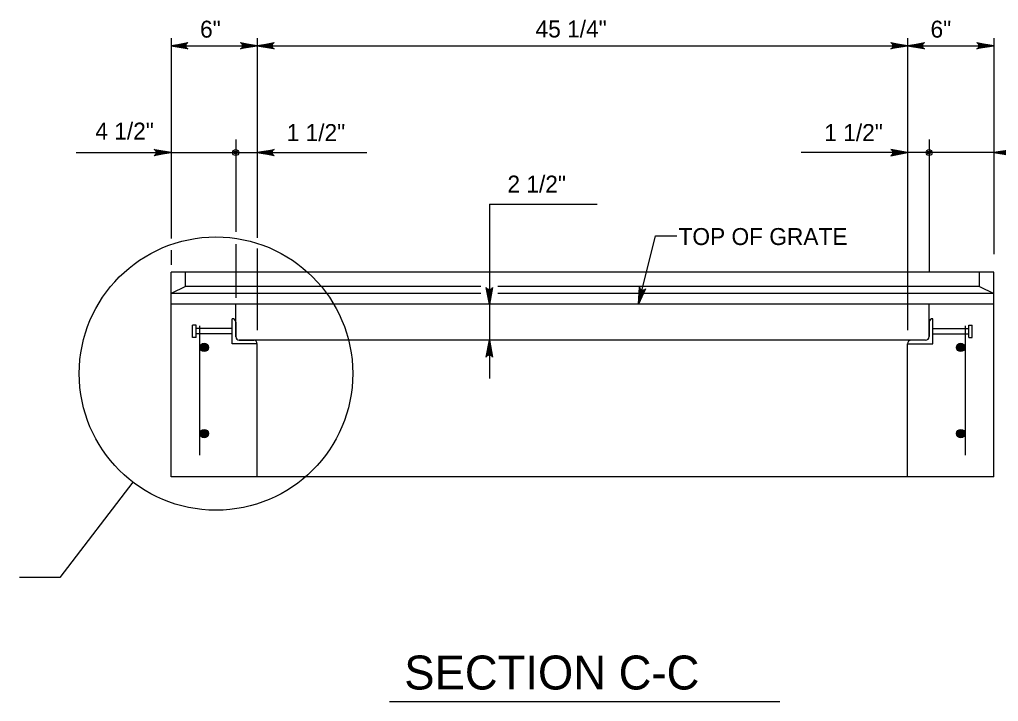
# Model space of a CAD drawing. Extents: x 2087776 to 2104538, y 970919 to 982612.
# Drawn here: x 2094744 to 2095312, y 981338 to 981734 of the extents above; entities that cross this region are included whole.
import ezdxf

# ---------------------------------------------------------------- set-up
doc = ezdxf.new("R2010")
doc.units = 0
doc.layers.add('1', color=7, linetype='Continuous')

msp = doc.modelspace()

# ---------------------------------------------------------------- linework, layer by layer
at = {"layer": '1'}
for p, q in [((2094831.77, 981722.86), (2094831.77, 981606.57)), ((2094881.77, 981722.86), (2094881.77, 981607.02)), ((2095258.86, 981722.86), (2095258.86, 981553.42)), ((2095308.85, 981722.86), (2095308.85, 981597.51)), ((2094831.77, 981718.46), (2095308.85, 981718.46)), ((2094869.27, 981664.01), (2094869.27, 981610.58)), ((2095271.36, 981664.01), (2095271.36, 981587.33)), ((2094776.78, 981656.53), (2094945.26, 981656.53)), ((2095370.41, 981656.53), (2095197.18, 981656.53)), ((2095016.35, 981626.49), (2095016.35, 981525.48)), ((2095016.35, 981626.49), (2095078.81, 981626.49)), ((2094869.27, 981603.46), (2094869.27, 981572.27)), ((2094831.77, 981599.9), (2094831.77, 981591.41)), ((2094881.77, 981600.79), (2094881.77, 981553.42)), ((2094831.77, 981468.46), (2094831.77, 981587.21)), ((2095308.85, 981587.21), (2094831.77, 981587.21)), ((2094840.1, 981578.87), (2094840.1, 981587.21)), ((2095300.52, 981578.87), (2095300.52, 981587.21)), ((2095308.85, 981468.46), (2095308.85, 981587.21)), ((2094840.1, 981578.87), (2094831.77, 981574.71)), ((2095011.44, 981574.71), (2094831.77, 981574.71)), ((2095011.44, 981578.87), (2094840.1, 981578.87)), ((2095300.52, 981578.87), (2095021.18, 981578.87)), ((2095308.85, 981574.71), (2095021.18, 981574.71)), ((2095300.52, 981578.87), (2095308.85, 981574.71)), ((2095308.85, 981568.46), (2094831.77, 981568.46)), ((2094869.27, 981549.66), (2094869.27, 981568.46)), ((2095271.36, 981549.72), (2095271.36, 981568.46)), ((2094867.19, 981545.54), (2094867.19, 981560.12)), ((2094869.27, 981558.04), (2094869.27, 981549.71)), ((2095271.36, 981558.04), (2095271.36, 981549.71)), ((2095273.44, 981545.54), (2095273.44, 981560.12)), ((2094846.27, 981556.39), (2094844.27, 981556.39)), ((2094844.27, 981549.27), (2094844.27, 981556.39)), ((2094846.27, 981549.27), (2094846.27, 981556.39)), ((2094867.19, 981554.39), (2094846.27, 981554.39)), ((2094848.44, 981480.96), (2094848.44, 981555.96)), ((2095273.44, 981554.39), (2095294.35, 981554.39)), ((2095292.18, 981555.96), (2095292.18, 981480.96)), ((2095294.35, 981556.39), (2095296.35, 981556.39)), ((2095294.35, 981549.27), (2095294.35, 981556.39)), ((2095296.35, 981549.27), (2095296.35, 981556.39)), ((2094844.27, 981549.27), (2094844.27, 981550.68)), ((2094846.27, 981549.27), (2094844.27, 981549.27)), ((2094846.27, 981549.27), (2094846.27, 981551.51)), ((2094867.19, 981551.27), (2094846.27, 981551.27)), ((2094880.72, 981547.63), (2094871.35, 981547.63)), ((2094871.35, 981547.63), (2094879.68, 981547.63)), ((2095263.14, 981547.63), (2094880.72, 981547.63)), ((2095269.28, 981547.63), (2095260.95, 981547.63)), ((2095273.44, 981551.27), (2095294.35, 981551.27)), ((2095294.35, 981549.27), (2095294.35, 981551.51)), ((2095294.35, 981549.27), (2095296.35, 981549.27)), ((2095296.35, 981549.27), (2095296.35, 981550.68)), ((2094881.77, 981545.54), (2094867.19, 981545.54)), ((2094881.77, 981468.46), (2094881.77, 981545.54)), ((2095258.86, 981468.46), (2095258.86, 981545.54)), ((2095258.86, 981545.54), (2095273.44, 981545.54)), ((2095308.85, 981468.46), (2094831.77, 981468.46)), ((2094809.63, 981465.3), (2094767.27, 981409.94)), ((2094767.27, 981409.94), (2094743.92, 981409.94)), ((2094958.39, 981338.05), (2095184.8, 981338.05))]:
    msp.add_line(p, q, dxfattribs=at)
for points in [[(2094831.77, 981718.46), (2094841.56, 981720.29), (2094841.18, 981720.03), (2094840.81, 981719.77), (2094840.61, 981719.44), (2094840.42, 981719.11), (2094840.36, 981718.79), (2094840.3, 981718.46), (2094840.36, 981718.13), (2094840.42, 981717.8), (2094840.61, 981717.47), (2094840.81, 981717.15), (2094841.18, 981716.88), (2094841.56, 981716.62), (2094831.77, 981718.46), (2094841.18, 981716.88), (2094840.81, 981717.15), (2094831.77, 981718.46), (2094840.61, 981717.47), (2094840.42, 981717.8), (2094831.77, 981718.46), (2094840.36, 981718.13), (2094840.3, 981718.46), (2094831.77, 981718.46), (2094840.36, 981718.79), (2094840.42, 981719.11), (2094831.77, 981718.46), (2094840.61, 981719.44), (2094840.81, 981719.77), (2094831.77, 981718.46), (2094841.18, 981720.03)], [(2094881.77, 981718.46), (2094871.98, 981716.62), (2094872.36, 981716.88), (2094872.73, 981717.15), (2094872.93, 981717.47), (2094873.12, 981717.8), (2094873.18, 981718.13), (2094873.24, 981718.46), (2094873.18, 981718.79), (2094873.12, 981719.11), (2094872.93, 981719.44), (2094872.73, 981719.77), (2094872.36, 981720.03), (2094871.98, 981720.29), (2094881.77, 981718.46), (2094872.36, 981720.03), (2094872.73, 981719.77), (2094881.77, 981718.46), (2094872.93, 981719.44), (2094873.12, 981719.11), (2094881.77, 981718.46), (2094873.18, 981718.79), (2094873.24, 981718.46), (2094881.77, 981718.46), (2094873.18, 981718.13), (2094873.12, 981717.8), (2094881.77, 981718.46), (2094872.93, 981717.47), (2094872.73, 981717.15), (2094881.77, 981718.46), (2094872.36, 981716.88)], [(2094881.77, 981718.46), (2094891.55, 981720.29), (2094891.17, 981720.03), (2094890.8, 981719.77), (2094890.6, 981719.44), (2094890.41, 981719.11), (2094890.35, 981718.79), (2094890.3, 981718.46), (2094890.35, 981718.13), (2094890.41, 981717.8), (2094890.6, 981717.47), (2094890.8, 981717.15), (2094891.17, 981716.88), (2094891.55, 981716.62), (2094881.77, 981718.46), (2094891.17, 981716.88), (2094890.8, 981717.15), (2094881.77, 981718.46), (2094890.6, 981717.47), (2094890.41, 981717.8), (2094881.77, 981718.46), (2094890.35, 981718.13), (2094890.3, 981718.46), (2094881.77, 981718.46), (2094890.35, 981718.79), (2094890.41, 981719.11), (2094881.77, 981718.46), (2094890.6, 981719.44), (2094890.8, 981719.77), (2094881.77, 981718.46), (2094891.17, 981720.03)], [(2095258.86, 981718.46), (2095249.08, 981716.62), (2095249.45, 981716.88), (2095249.83, 981717.15), (2095250.03, 981717.47), (2095250.22, 981717.8), (2095250.28, 981718.13), (2095250.33, 981718.46), (2095250.28, 981718.79), (2095250.22, 981719.11), (2095250.03, 981719.44), (2095249.83, 981719.77), (2095249.45, 981720.03), (2095249.08, 981720.29), (2095258.86, 981718.46), (2095249.45, 981720.03), (2095249.83, 981719.77), (2095258.86, 981718.46), (2095250.03, 981719.44), (2095250.22, 981719.11), (2095258.86, 981718.46), (2095250.28, 981718.79), (2095250.33, 981718.46), (2095258.86, 981718.46), (2095250.28, 981718.13), (2095250.22, 981717.8), (2095258.86, 981718.46), (2095250.03, 981717.47), (2095249.83, 981717.15), (2095258.86, 981718.46), (2095249.45, 981716.88)], [(2095258.86, 981718.46), (2095268.65, 981720.29), (2095268.27, 981720.03), (2095267.89, 981719.77), (2095267.7, 981719.44), (2095267.51, 981719.11), (2095267.45, 981718.79), (2095267.39, 981718.46), (2095267.45, 981718.13), (2095267.51, 981717.8), (2095267.7, 981717.47), (2095267.89, 981717.15), (2095268.27, 981716.88), (2095268.65, 981716.62), (2095258.86, 981718.46), (2095268.27, 981716.88), (2095267.89, 981717.15), (2095258.86, 981718.46), (2095267.7, 981717.47), (2095267.51, 981717.8), (2095258.86, 981718.46), (2095267.45, 981718.13), (2095267.39, 981718.46), (2095258.86, 981718.46), (2095267.45, 981718.79), (2095267.51, 981719.11), (2095258.86, 981718.46), (2095267.7, 981719.44), (2095267.89, 981719.77), (2095258.86, 981718.46), (2095268.27, 981720.03)], [(2095308.85, 981718.46), (2095299.07, 981716.62), (2095299.45, 981716.88), (2095299.82, 981717.15), (2095300.02, 981717.47), (2095300.21, 981717.8), (2095300.27, 981718.13), (2095300.32, 981718.46), (2095300.27, 981718.79), (2095300.21, 981719.11), (2095300.02, 981719.44), (2095299.82, 981719.77), (2095299.45, 981720.03), (2095299.07, 981720.29), (2095308.85, 981718.46), (2095299.45, 981720.03), (2095299.82, 981719.77), (2095308.85, 981718.46), (2095300.02, 981719.44), (2095300.21, 981719.11), (2095308.85, 981718.46), (2095300.27, 981718.79), (2095300.32, 981718.46), (2095308.85, 981718.46), (2095300.27, 981718.13), (2095300.21, 981717.8), (2095308.85, 981718.46), (2095300.02, 981717.47), (2095299.82, 981717.15), (2095308.85, 981718.46), (2095299.45, 981716.88)], [(2094831.77, 981656.53), (2094821.99, 981654.7), (2094822.37, 981654.96), (2094822.74, 981655.22), (2094822.94, 981655.55), (2094823.13, 981655.88), (2094823.19, 981656.21), (2094823.24, 981656.53), (2094823.19, 981656.86), (2094823.13, 981657.19), (2094822.94, 981657.52), (2094822.74, 981657.85), (2094822.37, 981658.11), (2094821.99, 981658.37), (2094831.77, 981656.53), (2094822.37, 981658.11), (2094822.74, 981657.85), (2094831.77, 981656.53), (2094822.94, 981657.52), (2094823.13, 981657.19), (2094831.77, 981656.53), (2094823.19, 981656.86), (2094823.24, 981656.53), (2094831.77, 981656.53), (2094823.19, 981656.21), (2094823.13, 981655.88), (2094831.77, 981656.53), (2094822.94, 981655.55), (2094822.74, 981655.22), (2094831.77, 981656.53), (2094822.37, 981654.96)], [(2094881.77, 981656.53), (2094891.55, 981658.37), (2094891.17, 981658.11), (2094890.8, 981657.85), (2094890.6, 981657.52), (2094890.41, 981657.19), (2094890.35, 981656.86), (2094890.3, 981656.53), (2094890.35, 981656.21), (2094890.41, 981655.88), (2094890.6, 981655.55), (2094890.8, 981655.22), (2094891.17, 981654.96), (2094891.55, 981654.7), (2094881.77, 981656.53), (2094891.17, 981654.96), (2094890.8, 981655.22), (2094881.77, 981656.53), (2094890.6, 981655.55), (2094890.41, 981655.88), (2094881.77, 981656.53), (2094890.35, 981656.21), (2094890.3, 981656.53), (2094881.77, 981656.53), (2094890.35, 981656.86), (2094890.41, 981657.19), (2094881.77, 981656.53), (2094890.6, 981657.52), (2094890.8, 981657.85), (2094881.77, 981656.53), (2094891.17, 981658.11)], [(2095258.86, 981656.53), (2095249.08, 981658.37), (2095249.45, 981658.11), (2095249.83, 981657.85), (2095250.03, 981657.52), (2095250.22, 981657.19), (2095250.28, 981656.86), (2095250.33, 981656.53), (2095250.28, 981656.21), (2095250.22, 981655.88), (2095250.03, 981655.55), (2095249.83, 981655.22), (2095249.45, 981654.96), (2095249.08, 981654.7), (2095258.86, 981656.53), (2095249.45, 981654.96), (2095249.83, 981655.22), (2095258.86, 981656.53), (2095250.03, 981655.55), (2095250.22, 981655.88), (2095258.86, 981656.53), (2095250.28, 981656.21), (2095250.33, 981656.53), (2095258.86, 981656.53), (2095250.28, 981656.86), (2095250.22, 981657.19), (2095258.86, 981656.53), (2095250.03, 981657.52), (2095249.83, 981657.85), (2095258.86, 981656.53), (2095249.45, 981658.11)], [(2095308.85, 981656.53), (2095318.64, 981658.37)], [(2095317.89, 981657.85), (2095308.85, 981656.53), (2095318.26, 981658.11)], [(2095317.5, 981657.19), (2095308.85, 981656.53), (2095317.69, 981657.52)], [(2095317.38, 981656.53), (2095308.85, 981656.53), (2095317.44, 981656.86)], [(2095318.64, 981654.7), (2095308.85, 981656.53), (2095318.26, 981654.96)], [(2095317.89, 981655.22), (2095308.85, 981656.53), (2095317.69, 981655.55)], [(2095317.5, 981655.88), (2095308.85, 981656.53), (2095317.44, 981656.21)], [(2095102.85, 981568.46), (2095112.6, 981608.17), (2095125, 981608.17)], [(2095016.35, 981568.46), (2095014.51, 981578.24), (2095014.77, 981577.87), (2095015.03, 981577.49), (2095015.36, 981577.29), (2095015.69, 981577.1), (2095016.02, 981577.04), (2095016.35, 981576.99), (2095016.67, 981577.04), (2095017, 981577.1), (2095017.33, 981577.29), (2095017.66, 981577.49), (2095017.92, 981577.87), (2095018.18, 981578.24), (2095016.35, 981568.46), (2095017.92, 981577.87), (2095017.66, 981577.49), (2095016.35, 981568.46), (2095017.33, 981577.29), (2095017, 981577.1), (2095016.35, 981568.46), (2095016.67, 981577.04), (2095016.35, 981576.99), (2095016.35, 981568.46), (2095016.02, 981577.04), (2095015.69, 981577.1), (2095016.35, 981568.46), (2095015.36, 981577.29), (2095015.03, 981577.49), (2095016.35, 981568.46), (2095014.77, 981577.87)], [(2095102.85, 981568.46), (2095103.4, 981578.32), (2095103.56, 981577.9), (2095103.72, 981577.47), (2095103.99, 981577.21), (2095104.26, 981576.94), (2095104.57, 981576.81), (2095104.87, 981576.68), (2095105.2, 981576.65), (2095105.53, 981576.63), (2095105.89, 981576.74), (2095106.25, 981576.85), (2095106.59, 981577.15), (2095106.93, 981577.45), (2095102.85, 981568.46), (2095106.59, 981577.15), (2095106.25, 981576.85), (2095102.85, 981568.46), (2095105.89, 981576.74), (2095105.53, 981576.63), (2095102.85, 981568.46), (2095105.2, 981576.65), (2095104.87, 981576.68), (2095102.85, 981568.46), (2095104.57, 981576.81), (2095104.26, 981576.94), (2095102.85, 981568.46), (2095103.99, 981577.21), (2095103.72, 981577.47), (2095102.85, 981568.46), (2095103.56, 981577.9)], [(2095016.35, 981547.63), (2095018.18, 981537.84), (2095017.92, 981538.22), (2095017.66, 981538.6), (2095017.33, 981538.79), (2095017, 981538.98), (2095016.67, 981539.04), (2095016.35, 981539.1), (2095016.02, 981539.04), (2095015.69, 981538.98), (2095015.36, 981538.79), (2095015.03, 981538.6), (2095014.77, 981538.22), (2095014.51, 981537.84), (2095016.35, 981547.63), (2095014.77, 981538.22), (2095015.03, 981538.6), (2095016.35, 981547.63), (2095015.36, 981538.79), (2095015.69, 981538.98), (2095016.35, 981547.63), (2095016.02, 981539.04), (2095016.35, 981539.1), (2095016.35, 981547.63), (2095016.67, 981539.04), (2095017, 981538.98), (2095016.35, 981547.63), (2095017.33, 981538.79), (2095017.66, 981538.6), (2095016.35, 981547.63), (2095017.92, 981538.22)]]:
    msp.add_lwpolyline(points, dxfattribs=at)
for centre, radius in [((2094869.27, 981656.53), 1.75), ((2094869.27, 981656.53), 0.875), ((2095271.36, 981656.53), 1.75), ((2095271.36, 981656.53), 0.875), ((2094857.81, 981528.28), 79.29), ((2094851, 981543.46), 2.45), ((2094851, 981543.46), 2.27), ((2094851, 981543.46), 2.1), ((2094851, 981543.46), 1.93), ((2094851, 981543.46), 1.75), ((2094851, 981543.46), 1.58), ((2094851, 981543.46), 1.4), ((2094851, 981543.46), 1.23), ((2094851, 981543.46), 1.06), ((2094851, 981543.46), 0.883), ((2094851, 981543.46), 0.709), ((2094851, 981543.46), 0.535), ((2094851, 981543.46), 0.361), ((2094851, 981543.46), 0.188), ((2095289.63, 981543.46), 2.45), ((2095289.63, 981543.46), 2.27), ((2095289.63, 981543.46), 2.1), ((2095289.63, 981543.46), 1.93), ((2095289.63, 981543.46), 1.75), ((2095289.63, 981543.46), 1.58), ((2095289.63, 981543.46), 1.4), ((2095289.63, 981543.46), 1.23), ((2095289.63, 981543.46), 1.06), ((2095289.63, 981543.46), 0.883), ((2095289.63, 981543.46), 0.709), ((2095289.63, 981543.46), 0.535), ((2095289.63, 981543.46), 0.361), ((2095289.63, 981543.46), 0.188), ((2094851, 981493.46), 2.45), ((2094851, 981493.46), 2.27), ((2094851, 981493.46), 2.1), ((2094851, 981493.46), 1.93), ((2094851, 981493.46), 1.75), ((2094851, 981493.46), 1.58), ((2095289.73, 981493.46), 2.45), ((2095289.73, 981493.46), 2.27), ((2095289.73, 981493.46), 2.1), ((2095289.73, 981493.46), 1.93), ((2095289.73, 981493.46), 1.75), ((2095289.73, 981493.46), 1.58), ((2094851, 981493.46), 1.4), ((2094851, 981493.46), 1.23), ((2094851, 981493.46), 1.06), ((2094851, 981493.46), 0.883), ((2094851, 981493.46), 0.709), ((2094851, 981493.46), 0.535), ((2094851, 981493.46), 0.361), ((2094851, 981493.46), 0.188), ((2095289.73, 981493.46), 1.4), ((2095289.73, 981493.46), 1.23), ((2095289.73, 981493.46), 1.06), ((2095289.73, 981493.46), 0.883), ((2095289.73, 981493.46), 0.709), ((2095289.73, 981493.46), 0.535), ((2095289.73, 981493.46), 0.361), ((2095289.73, 981493.46), 0.188)]:
    msp.add_circle(centre, radius, dxfattribs=at)
for centre, start, end in [((2094867.19, 981558.04), 360, 90), ((2095273.44, 981558.04), 90, 180), ((2094871.35, 981549.71), 180, 270), ((2094879.68, 981545.54), 0, 90), ((2095260.95, 981545.54), 90, 180), ((2095269.28, 981549.71), 270, 0)]:
    msp.add_arc(centre, 2.08, start, end, dxfattribs=at)

# ---------------------------------------------------------------- texts
for s, height, p in [('45 1/4"', 9.843, (2095043.13, 981723.31)), ('1 1/2"', 9.843, (2094898.81, 981663.19)), ('1 1/2"', 9.843, (2095210.57, 981663.19)), ('TOP OF GRATE', 9.8425, (2095126.03, 981602.86)), ('SECTION C-C', 19.685, (2094967, 981344.98))]:
    msp.add_text(s, height=height, dxfattribs=at).set_placement(p)
for s, p in [('6"', (2094848.58, 981723.2)), ('6"', (2095272.17, 981723.2)), ('4 1/2"', (2094787.84, 981664.04)), ('2 1/2"', (2095026.82, 981633.31))]:
    msp.add_text(s, height=9.843, rotation=360, dxfattribs=at).set_placement(p)

doc.saveas('drawing.dxf')
